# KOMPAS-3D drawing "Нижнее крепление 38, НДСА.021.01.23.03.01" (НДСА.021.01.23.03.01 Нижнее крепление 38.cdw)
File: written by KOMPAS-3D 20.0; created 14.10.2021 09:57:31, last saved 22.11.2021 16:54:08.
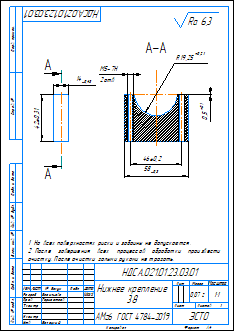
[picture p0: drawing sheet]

Sheet 1: A4, portrait

Document properties: Автор: adminzsc; Параметр неуказанной шероховатости: Ra 6,3; 281194922303: <item xmlns="http://appius.ru/pdm" xmlns:xs="http://www.w3.org/2001/XMLSchema" xmlns:xsi="http://www.w3.org/2001/XMLSchema-instance" xsi:type="item">  <element xmlns:d2p1="http://v8.1c.ru/8.1/data/enterprise/current-config" xsi:type="d2p1:CatalogRef.aps_Элемен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; 281194922503: <item xmlns="http://appius.ru/pdm" xmlns:xs="http://www.w3.org/2001/XMLSchema" xmlns:xsi="http://www.w3.org/2001/XMLSchema-instance" xsi:type="item">  <element xmlns:d2p1="http://v8.1c.ru/8.1/data/enterprise/current-config" xsi:type="d2p1:CatalogRef.aps_Элемен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; Полное имя файла: НДСА.021.01.23.03.01 Нижнее крепление 38.m3d; PLM_CDWXDTO: <item xmlns="http://appius.ru/pdm" xmlns:xs="http://www.w3.org/2001/XMLSchema" xmlns:xsi="http://www.w3.org/2001/XMLSchema-instance" xsi:type="item">  <element xmlns:d2p1="http://v8.1c.ru/8.1/data/enterprise/current-config" xsi:type="d2p1:CatalogRef.aps_Элемен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; Масса: 0.06626; PDM_DOCXDTO: <item xmlns="http://appius.ru/pdm" xmlns:xs="http://www.w3.org/2001/XMLSchema" xmlns:xsi="http://www.w3.org/2001/XMLSchema-instance" xsi:type="item">  <element xmlns:d2p1="http://v8.1c.ru/8.1/data/enterprise/current-config" xsi:type="d2p1:CatalogRef.aps_Элемен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; PDM_ITEMXDTO: <item xmlns="http://appius.ru/pdm" xmlns:xs="http://www.w3.org/2001/XMLSchema" xmlns:xsi="http://www.w3.org/2001/XMLSchema-instance" xsi:type="item">  <element xmlns:d2p1="http://v8.1c.ru/8.1/data/enterprise/current-config" xsi:type="d2p1:CatalogRef.aps_Элемен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; PDM_DRAWINGXDTO: <item xmlns="http://appius.ru/pdm" xmlns:xs="http://www.w3.org/2001/XMLSchema" xmlns:xsi="http://www.w3.org/2001/XMLSchema-instance" xsi:type="item">  <element xmlns:d2p1="http://v8.1c.ru/8.1/data/enterprise/current-config" xsi:type="d2p1:CatalogRef.aps_Элемен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

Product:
- Part/product: Нижнее крепление 38  | designation НДСА.021.01.23.03.01
    Материал: АМг6  ГОСТ 4784-2019 (density 2640 kg/m3)
    Масса: 0.0662558
    additional columns: <item xmlns="http://appius.ru/pdm" xmlns:xs="http://www.w3.org/2001/XMLSchema" x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; <item xmlns="http://appius.ru/pdm" xmlns:xs="http://www.w3.org/2001/XMLSchema" x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; <item xmlns="http://appius.ru/pdm" xmlns:xs="http://www.w3.org/2001/XMLSchema" x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; <item xmlns="http://appius.ru/pdm" xmlns:xs="http://www.w3.org/2001/XMLSchema" x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; <item xmlns="http://appius.ru/pdm" xmlns:xs="http://www.w3.org/2001/XMLSchema" x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
    source file: НДСА.002.01.06.01.00 Нижнее крепление 38.cdw, НДСА.021.01.23.03.01 Нижнее крепление 38.cdw

Title block, sheet 1: Наименование: Нижнее крепление / 38; designation: НДСА.021.01.23.03.01; Материал: АМг6  ГОСТ 4784-2019; Масса: 0,07 г; Количество листов документа: 1; organisation: ЭСТО; Форматы листов документа: A4; stored path: C:\Users\vasilyeva\Desktop\PM_APPIUS\НДСА.002.01.06.01.00 Нижнее крепление 38.cdw; Разработал: Васильева; Проверил: Горностаев; Утвердил: Белецкий; Разработал, date: 14.10.2021

Views: Вид 1, Спереди, Разрез А-А
Referenced files in C:\Users\vasilyeva\Desktop\PM_APPIUS\: НДСА.002.01.06.01.00 Нижнее крепление 38.m3d, НДСА.021.01.23.03.01 Нижнее крепление 38.m3d
Referenced files in C:\Users\s.pischagina\Desktop\PLM\: НДСА.021.01.23.03.01 Нижнее крепление 38.m3d
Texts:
  js14
  Ra 6,3
  НДСА.021.01.23.03.01 Нижнее крепление 38
Dimensions and other numbers on the sheet: 14; 42±0,31; 58; 46±0,2; 19,25; 0,5; -7Н; 5; 2отв; 1:1; 1; 38; 0,07 г; 14.10.2021

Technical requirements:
  На всех поверхностях риски и забоины не допускаются.
  После завершения всех процессов обработки произвести
  очистку. После очистки голыми руками не трогать.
